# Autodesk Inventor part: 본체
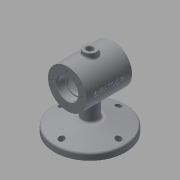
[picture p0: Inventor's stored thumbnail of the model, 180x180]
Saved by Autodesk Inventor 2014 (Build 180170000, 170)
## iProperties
Created: 2018-12
Part Number: 본체
Material: Generic
Document SubType Name: Modeling
Designer: kh
Density: 1 g/cm^3
Appearance: Default
Author: kh
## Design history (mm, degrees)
sketch "Sketch1"
  geometry: C1 r 55 at (0, 0); 1 further point
  constraints: 1 centre point, 1 coincident
  dimensions: "d0" = 110 diameter of C1
extrude "Extrusion1" new body sketch "Sketch1" distance "d1" = 10; taper "d2" = 0 deg
sketch "Sketch2"
  geometry: C1 r 55 at (0, 0); 1 further point
  constraints: 1 centre point, 1 coincident
  dimensions: "d3" = 110 diameter of C1
extrude "Extrusion2" join sketch "Sketch2" distance "d4" = 10; taper "d5" = -75 deg
sketch "Sketch4"
  geometry: L1 (0, 0)-(0, 75); C1 r 30 at (0, 75)
  constraints: 2 end point, 1 centre point, 1 coincident, 1 vertical
  dimensions: "d9" = 75 distance of L1.start L1.end; "d10" = 60 diameter of C1
extrude "Extrusion3" join sketch "Sketch4" stored distance "d11" = 70; taper "d12" = 0 deg
sketch "Sketch5"
  geometry: L1 (-35, 105)-(-35, 45) reference; L2 (-35, 75)-(35.231, 75); L3 (-35, 75)-(-35, 91); L4 (-35, 91)-(-23, 91); L5 (-23, 91)-(-23, 89); L6 (-23, 89)-(-20, 89); L7 (-20, 89)-(-20, 100); L8 (-20, 100)-(20, 100); L9 (20, 100)-(20, 89); L10 (20, 89)-(23, 89); L11 (23, 89)-(23, 91); L12 (35, 45)-(35, 105) reference; L13 (23, 91)-(35, 91); L14 (35, 75)-(35, 91); L15 (-35, 75)-(35, 75); 1 further point
  constraints: 26 end point, 6 parallel, 4 perpendicular, 2 midpoint, 2 point on line, 1 collinear
  dimensions: "d13" = 75 distance from line of L2 point (0, 0); "d14" = 12 distance between parallel lines of L5 L3; "d15" = 12 distance of L11.end L13.end; "d16" = 3 distance of L5.end L6.end; "d17" = 40 distance of L7.end L8.end; "d18" = 32 diameter of L4 L2; "d19" = 28 diameter of L6 L2; "d20" = 50 diameter of L8 L2; "d21" = 28 diameter of L10 L2; "d22" = 32 diameter of L13 L2
revolve "Revolution1" sketch "Sketch5" stored, may be unused: angle "d23" = 90 deg
sketch "Sketch6"
  geometry: C1 r 12 at (0, 0); 1 further point
  constraints: 1 centre point, 1 coincident
  dimensions: "d24" = 24 diameter of C1
extrude "Extrusion4" join sketch "Sketch6" stored distance "d25" = 10; taper "d26" = 0 deg
chamfer "Chamfer1" distance "d27" = 1; stored, may be unused: second distance "d28" = 2, angle "d29" = 45 deg
fillet "Fillet1" dims "d30" = 0.3, "d31" = 3
sketch "Sketch7" dims "d32" = 46
  geometry: L1 (0, 0)-(0, 23); C1 r 17 at (0, 0) reference; 8 further points
  constraints: 5 coincident, 2 end point, 1 vertical, 1 vertical alignment, 11 other
  dimensions: "d35" = 360 deg dimension on C1.centre L1.end (derived)
hole "Hole1" sketch "Sketch7" at (0, 23), (-23, 0), (0, -23), (23, 0) diameter "d37" = 3.242; stored, may be unused: countersink angle "d41" = 90 deg, drill point angle "d43" = 118 deg; dims "d38" = 8, "d39" = 4, "d40" = 2, "d42" = 10
mirror "Mirror1"
fillet "Fillet2" dims "d49" = 3
workplane "Work Plane2"
sketch "Sketch9"
  geometry: C1 r 10 at (0, 0); C2 r 5 at (0, 0); 1 further point
  constraints: 2 centre point, 2 coincident
  dimensions: "d51" = 20 diameter of C1; "d54" = 10 diameter of C2
extrude "Extrusion5" join sketch "Sketch9" stored distance "d52" = 10; taper "d53" = 0 deg
extrude "Extrusion6" cut sketch "Sketch9" distance "d55" = 30; taper "d56" = 0 deg
chamfer "Chamfer2" distance "d57" = 1; stored, may be unused: second distance "d58" = 2, angle "d59" = 45 deg
fillet "Fillet3" dims "d60" = 3
workplane "Work Plane3"
sketch "Sketch10"
  geometry: L1 (-35, 105)-(-35, 45) reference; L2 (-35, 75)-(25.972, 75); L3 (-35, 105)-(35, 105) reference; L4 (10, 112)-(-10, 112) reference; L5 (0, 112)-(0, 75); L6 (-24.763, 79.724)-(25.011, 79.724); L7 (25.011, 79.724)-(25.011, 72.519); L8 (25.011, 72.519)-(-24.763, 72.519); L9 (-24.763, 72.519)-(-24.763, 79.724); 1 further point
  constraints: 4 end point, 2 midpoint, 2 perpendicular, 1 point on line, 2 other
emboss "Emboss1" sketch "Sketch10" dims "d13" = 75, "d14" = 12, "d15" = 12, "d16" = 3, "d17" = 40, "d18" = 32, "d19" = 28, "d20" = 50, "d21" = 28, "d22" = 32, "d62" = 0.5, "d63" = 0
sketch "Sketch11" dims "d64" = 88
  geometry: C1 r 55 at (0, 0) reference; 6 further points
  constraints: 1 coincident, 1 vertical alignment, 7 other
  dimensions: "d67" = 360 deg dimension on point (0, 0) point (0, 44) (derived)
hole "Hole2" sketch "Sketch11" at (0, 44), (-44, 0), (0, -44), (44, 0) diameter "d69" = 9; stored, may be unused: countersink angle "d73" = 90 deg, drill point angle "d75" = 118 deg; dims "d70" = 10, "d71" = 14, "d72" = 2, "d74" = 10
workplane "Work Plane4"
sketch "Sketch12" dims "d77" = 88
  geometry: L1 (0, 0)-(0, 44); C1 r 55 at (0, 0) reference; 5 further points
  constraints: 2 coincident, 2 end point, 1 vertical, 1 vertical alignment, 7 other
  dimensions: "d80" = 360 deg dimension on point (0, 0) point (0, 44) (derived)
fillet "Fillet4" dims "d82" = 3
body "Solid1"
other parameters: "d50" = -112, "d61" = 94.5
